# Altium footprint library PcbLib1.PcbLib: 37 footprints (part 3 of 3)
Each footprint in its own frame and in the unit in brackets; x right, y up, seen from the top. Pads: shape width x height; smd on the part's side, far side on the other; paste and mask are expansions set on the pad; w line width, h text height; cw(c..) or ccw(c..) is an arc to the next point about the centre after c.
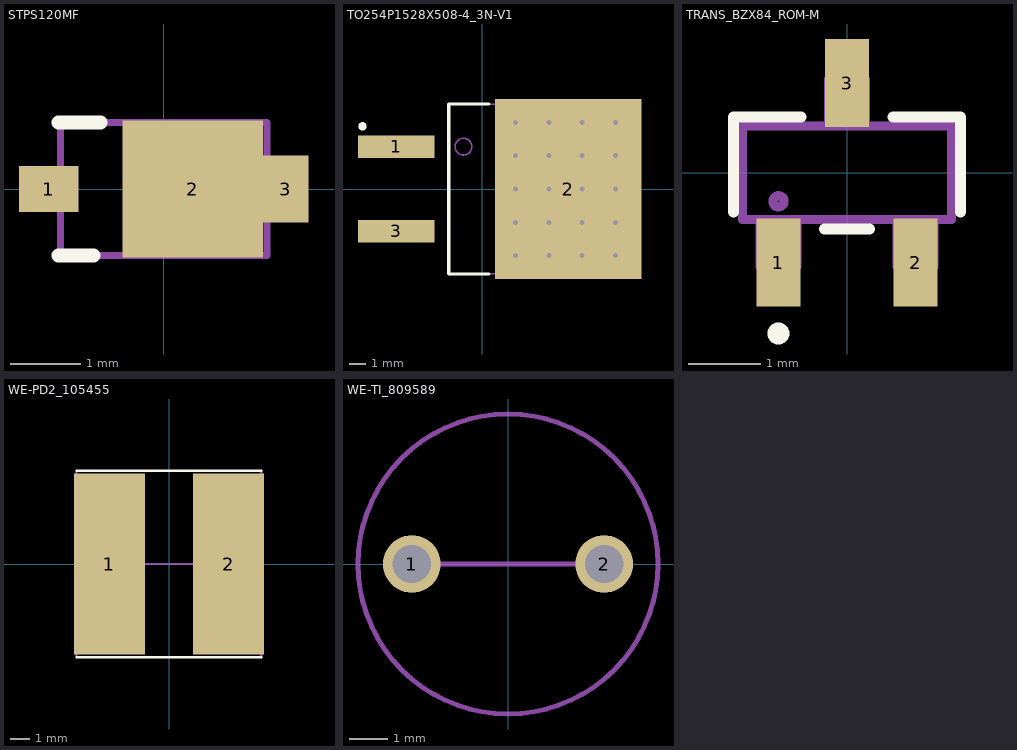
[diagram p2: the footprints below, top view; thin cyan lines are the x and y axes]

## STPS120MF [mm]
pads (3):
  rect 0.85x0.65 smd: 1(-1.64,0)
  rect 2x1.95 smd: 2(0.415,0)
  rect 0.65x0.95 smd: 3(1.74,0)
Top Overlay:
  lines w0.2: -1.5,-0.95 -1,-0.95 ; -1.5,0.95 -0.9,0.95
Mechanical 13:
  lines w0.1: -1.475,-0.95 -1.475,0.95 1.475,0.95 1.475,-0.95 -1.475,-0.95
  text ".Designator" at -1.788,-0.428 h1.1
3D body "STPS120MF.stp": height 0.85, standoff 0, extent -1.855,-0.961 1.945,0.961

## TO254P1528X508-4_3N-V1 [mm] "TO,2.54mm pitch;3 pin,15.28mm L X 9.00mm W X 5.08mm H body"
height 5.08
pads (3):
  rect 4.6x1.35 smd paste-0.05 mask+0: 1(-5.155,2.54) 3(-5.155,-2.54)
  rect 8.8x10.8 smd paste-4.4 mask+0: 2(5.155,0)
via 8,-2 diameter 0.7 hole 0.3
via 8,4 diameter 0.7 hole 0.3
via 8,2 diameter 0.7 hole 0.3
via 8,0 diameter 0.7 hole 0.3
via 8,-4 diameter 0.7 hole 0.3
via 6,-2 diameter 0.7 hole 0.3
via 6,4 diameter 0.7 hole 0.3
via 6,2 diameter 0.7 hole 0.3
via 6,0 diameter 0.7 hole 0.3
via 6,-4 diameter 0.7 hole 0.3
via 4,-2 diameter 0.7 hole 0.3
via 4,4 diameter 0.7 hole 0.3
via 4,2 diameter 0.7 hole 0.3
via 4,0 diameter 0.7 hole 0.3
via 4,-4 diameter 0.7 hole 0.3
via 2,-2 diameter 0.7 hole 0.3
via 2,4 diameter 0.7 hole 0.3
via 2,2 diameter 0.7 hole 0.3
via 2,0 diameter 0.7 hole 0.3
via 2,-4 diameter 0.7 hole 0.3
Top Overlay:
  circle w0.25: c-7.188,3.765 r0.125
  lines w0.2: 0.4,-5.1 -2,-5.1 -2,5.1 0.4,5.1
Top Paste:
  region: 5.305,-0.15 9.505,-0.15 9.505,-5.35 5.305,-5.35
  region: 0.805,-0.15 5.005,-0.15 5.005,-5.35 0.805,-5.35
  region: 5.305,0.15 9.505,0.15 9.505,5.35 5.305,5.35
  region: 0.805,5.35 5.005,5.35 5.005,0.15 0.805,0.15
Mechanical 13:
  circle w0.1: c-1.125,2.54 r0.5
  lines w0.1: -1.986,-5.08 7.014,-5.08 7.014,5.08 -1.986,5.08 -1.986,-5.08
  text ".Designator" at -1.238,-0.328 h1.1
3D body "PG-TO263-3-901_Z8B00200767_V01_3D.stp": height 5.09, standoff 0, extent -6.59,-5.08 8.69,5.08

## TRANS_BZX84_ROM-M [mil]
pads (3):
  rect 24x48 smd paste+0 mask+0: 1(-37.4,-49) 2(37.4,-49) 3(0,49)
Top Overlay:
  circle w6: c-37.4,-87.6 r3
  lines w6: -62,-21.41 -62,30.5 -25.1,30.5 ; -12.3,-30.5 12.3,-30.5 ; 25.1,30.5 62,30.5 62,-21.41
Mechanical 13:
  circle w5: c-37.4,-15.5 r3
  lines w5: -57,-25.5 57,-25.5 57,25.5 -57,25.5 -57,-25.5 ; -47.4,-51 -47.4,-25.5 -27.4,-25.5 -27.4,-51 -47.4,-51 ; -10,25.5 10,25.5 10,51 -10,51 -10,25.5 ; 27.4,-51 27.4,-25.5 47.4,-25.5 47.4,-51 27.4,-51
  text ".Designator" at -39.53,-15.95 h43.31
3D body "TRANS_BZX84_ROM.step": height 45.12, standoff 0, extent -57.01,-50.98 57.01,50.98

## WE-PD2_105455 [mm]
pads (2):
  rect 3.75x9.5 smd: 1(-3.125,0) 2(3.125,0)
Top Overlay:
  lines w0.127: -4.858,-4.895 4.84,-4.895 ; -4.858,4.895 4.84,4.895
Mechanical 13:
  lines w0.127: -4.858,-4.895 -4.858,4.895 ; -3.125,0 3.125,0 ; 4.84,-4.895 4.84,4.895
  text ".Designator" at -4.538,0.347 h1.1
3D body "744776112.stp": height 5.4, standoff 0, extent -5.045,-4.5 5.045,4.5

## WE-TI_809589 [mm]
pads (2):
  round 1.5 hole 1: 1(-2.5,0) 2(2.5,0)
Mechanical 13:
  circle w0.127: c0,0 r3.9
  lines w0.127: -2.5,0 2.5,0
  text ".Designator" at -3.488,0.322 h1.1
3D body "7447720150.stp": height 9.38, standoff -5.12, extent -3.9,-3.9 3.9,3.9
